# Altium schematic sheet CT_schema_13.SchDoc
size 387 x 385 mm
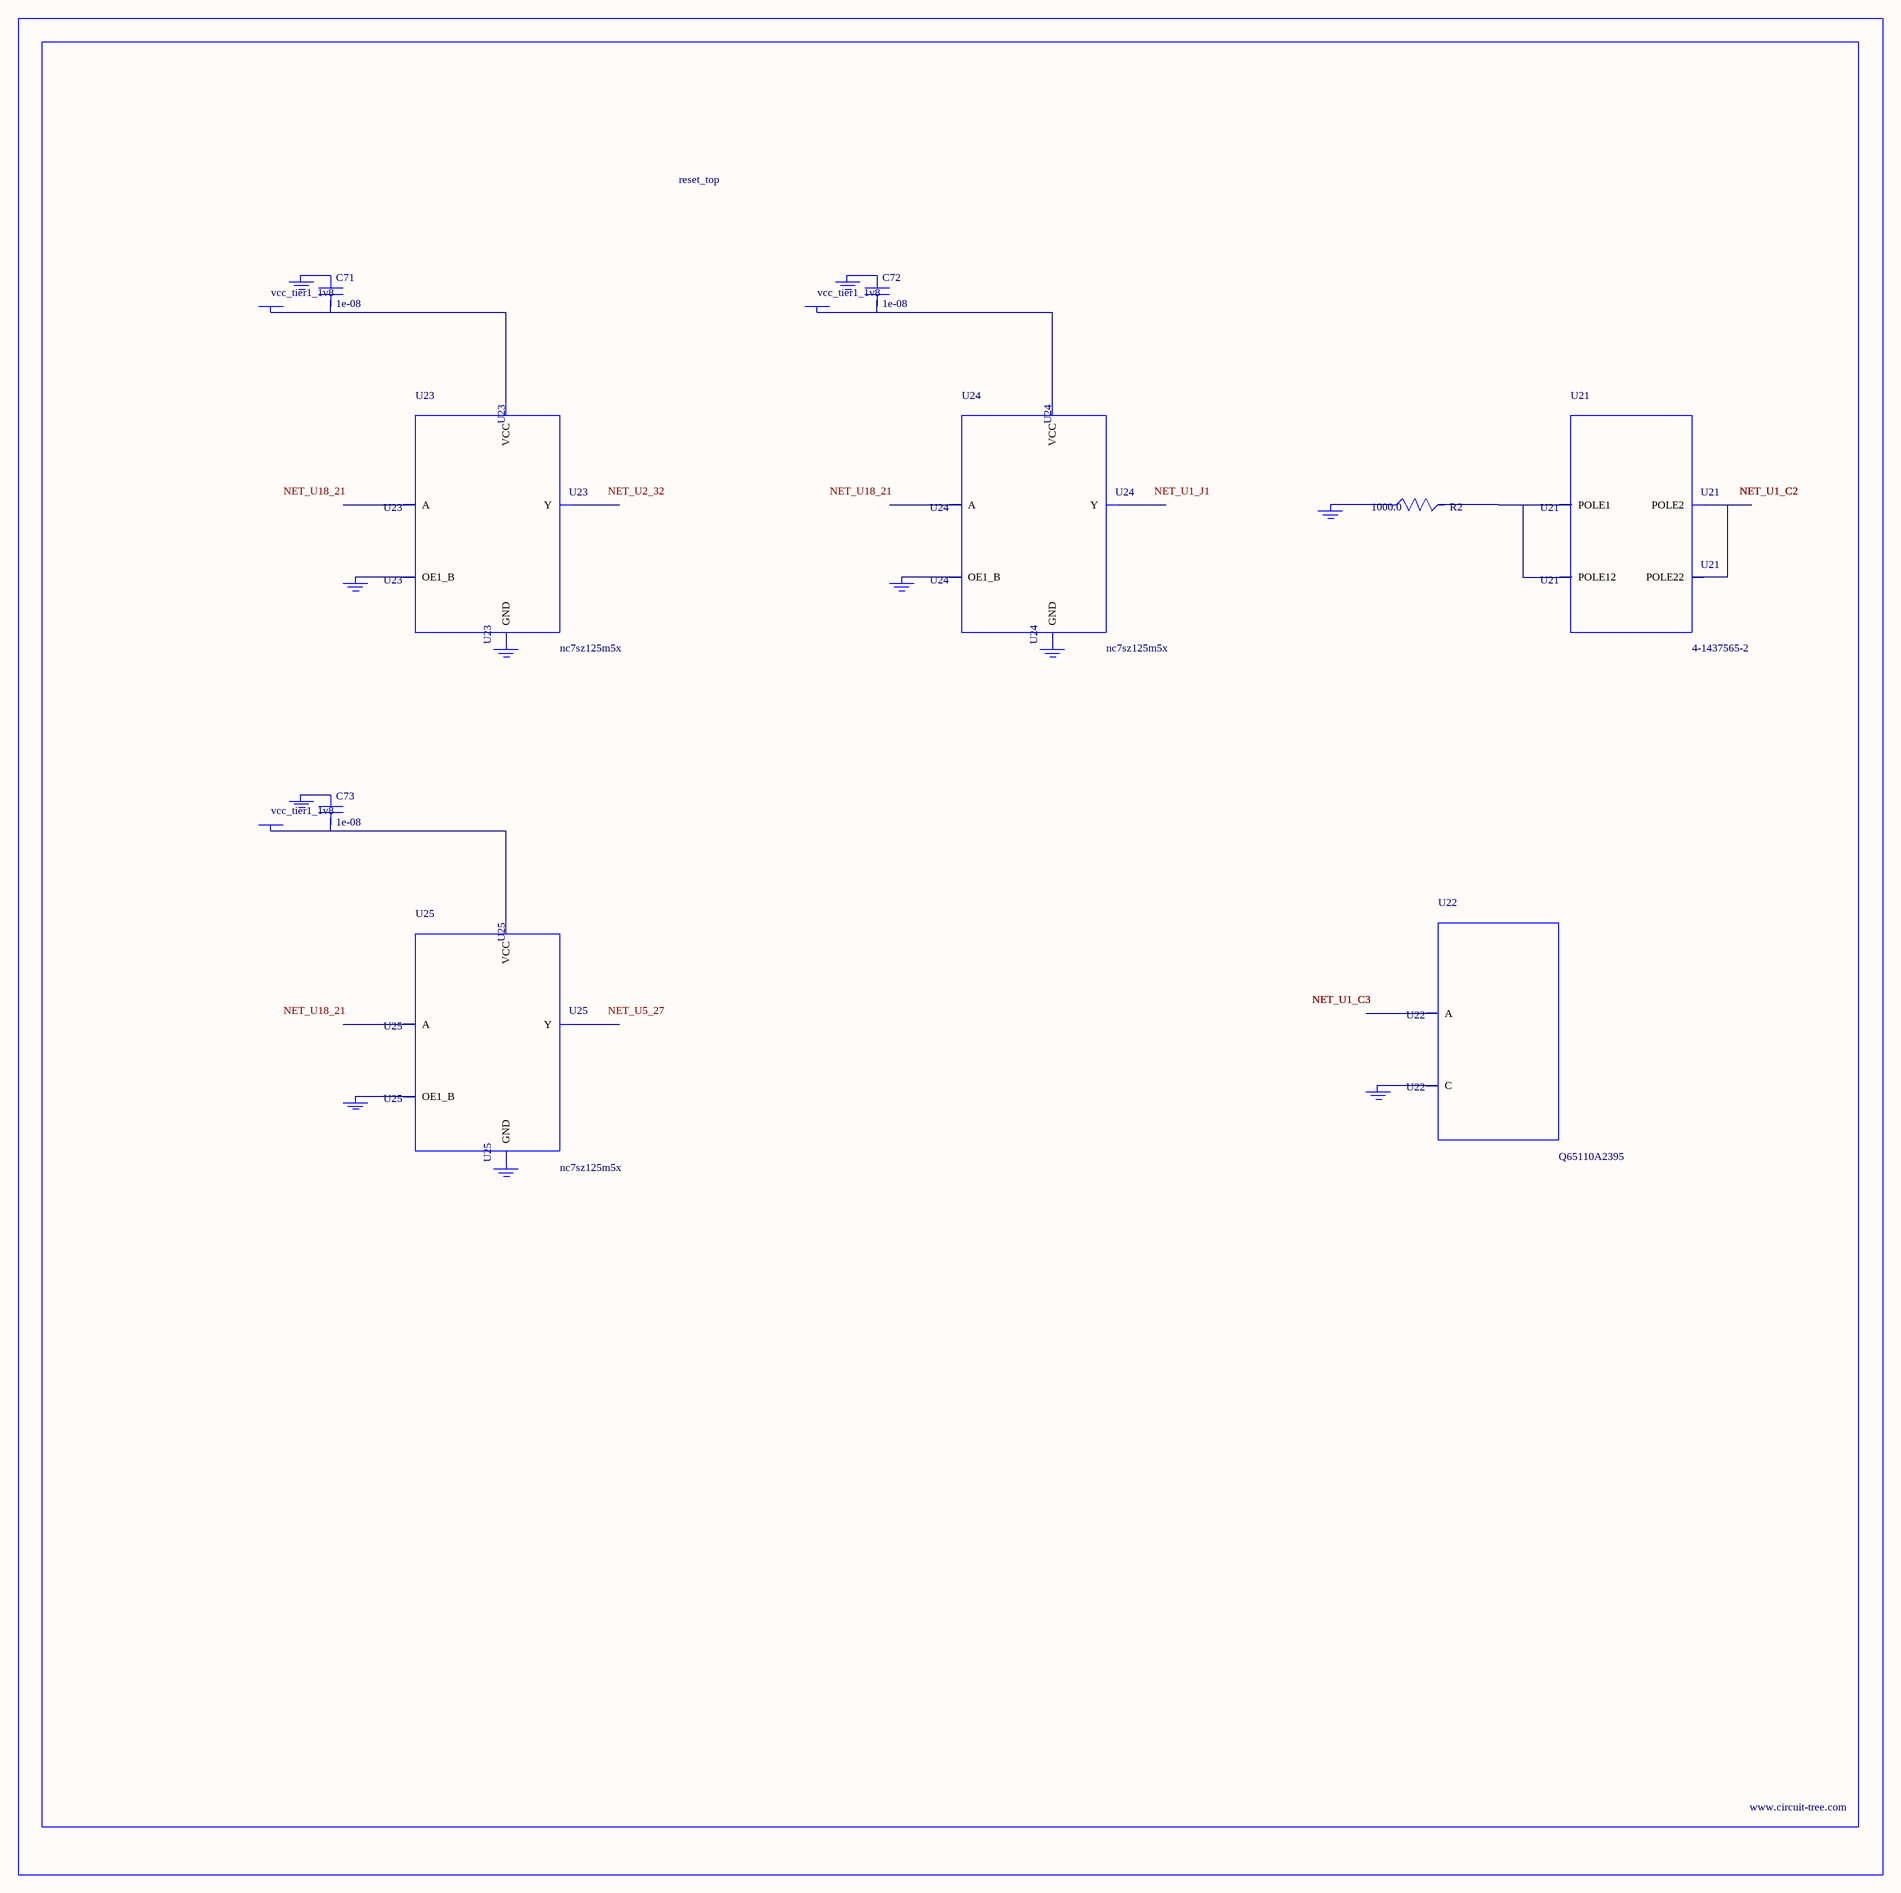
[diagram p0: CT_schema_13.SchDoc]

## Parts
BORDER12  (no value)
C71  1e-08  [C0402]
C72  1e-08  [C0402]
C73  1e-08  [C0402]
GND_INSTANCE_12_0  (no value)
GND_INSTANCE_12_1  (no value)
GND_INSTANCE_12_2  (no value)
GND_INSTANCE_12_3  (no value)
GND_INSTANCE_12_4  (no value)
GND_INSTANCE_12_5  (no value)
GND_INSTANCE_12_6  (no value)
GND_INSTANCE_12_7  (no value)
GND_INSTANCE_12_8  (no value)
GND_INSTANCE_12_9  (no value)
GND_INSTANCE_12_10  (no value)
POWER_INSTANCE_12_0  vcc_tier1_1v8
POWER_INSTANCE_12_1  vcc_tier1_1v8
POWER_INSTANCE_12_2  vcc_tier1_1v8
R2  1000.0  [R0603]
U21  4-1437565-2  [SW_4-1437565-2]
U22  Q65110A2395  [LGM67K-G1J2-24-Z]
U23  nc7sz125m5x  [NC7SZ125M5X]
U24  nc7sz125m5x  [NC7SZ125M5X]
U25  nc7sz125m5x  [NC7SZ125M5X]

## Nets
NetC71_1: C71.1 GND_INSTANCE_12_2.0(GND)
NetC71_2: C71.2 POWER_INSTANCE_12_0.0(PWR) U23.5(VCC)
NetC72_1: C72.1 GND_INSTANCE_12_5.0(GND)
NetC72_2: C72.2 POWER_INSTANCE_12_1.0(PWR) U24.5(VCC)
NetC73_1: C73.1 GND_INSTANCE_12_8.0(GND)
NetC73_2: C73.2 POWER_INSTANCE_12_2.0(PWR) U25.5(VCC)
NetGND_INSTANCE_12_0_0: GND_INSTANCE_12_0.0(GND) R2.1
NetGND_INSTANCE_12_1_0: GND_INSTANCE_12_1.0(GND) U22.C
NetGND_INSTANCE_12_3_0: GND_INSTANCE_12_3.0(GND) U23.1(OE1_B)
NetGND_INSTANCE_12_4_0: GND_INSTANCE_12_4.0(GND) U23.3(GND)
NetGND_INSTANCE_12_6_0: GND_INSTANCE_12_6.0(GND) U24.1(OE1_B)
NetGND_INSTANCE_12_7_0: GND_INSTANCE_12_7.0(GND) U24.3(GND)
NetGND_INSTANCE_12_9_0: GND_INSTANCE_12_9.0(GND) U25.1(OE1_B)
NetGND_INSTANCE_12_10_0: GND_INSTANCE_12_10.0(GND) U25.3(GND)
NetR2_2: R2.2 U21.1(POLE1) U21.2(POLE12)
NetU21_3: U21.3(POLE2) U21.4(POLE22)

Not connected (* = marked no-connect by the designer): U22 A; U23 2(A) 4(Y); U24 2(A) 4(Y); U25 2(A) 4(Y)

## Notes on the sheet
- Labels drawn without touching a wire or pin: NET_U1_J1, NET_U2_32, NET_U5_27, NET_U18_21

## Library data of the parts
BORDER12 = BORDER_PAGE12
C71-C73 = C0402C103K3RAC
GND_INSTANCE_12_0-GND_INSTANCE_12_10 = GND
POWER_INSTANCE_12_0-POWER_INSTANCE_12_2 = PWR
R2 = RC0603JR-071KL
